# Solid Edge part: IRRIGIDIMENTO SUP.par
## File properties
Subject: IRRIGIDIMENTO SUP
Author: f_grande
Template: Normal.par
Last saved by: f_grande
Revision: 2
Application: Solid Edge
Material: MDF
Stile della faccia: Marroncino
Coef. of Thermal Exp: 0.0
Thermal Conductivity: 0.0
Specific Heat: 0.0
Modulus of Elasticity: 0.0
Poisson's Ratio: 0.0
Yield Stress: 0.0
Ultimate Stress: 0.0
Elongation: 0.0
Tipo di contenuto documento: 0
Densità: 750,000 kg/m^3
Precisione: 0,990
Document Number: KR0150
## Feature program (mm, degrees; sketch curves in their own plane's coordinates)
sketch for "unnamed Protrusion 1" plane through (0, 0, 0) normal (0, -1, 0) x-axis (1, 0, 0)
  line (-64.5, 20) -> (64.5, 20)
  line (64.5, 20) -> (64.5, -20)
  line (64.5, -20) -> (-64.5, -20)
  line (-64.5, -20) -> (-64.5, 20)
  dimension (linear) = 64.5
  dimension (linear) = 64.5
extrude "unnamed Protrusion 1" add finite 19 symmetric
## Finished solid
Body 1: solid body, 6 faces, 12 edges, 8 vertices.
  Faces by surface: plane 6
  Edges by curve: line 12
Bounding box of the edges (mm): 129.000 x 19.000 x 40.000, from (-64.5, -9.5, -20) to (64.5, 9.5, 20).
Planar faces by outward normal: +x 1, +y 1, +z 1, -x 1, -y 1, -z 1
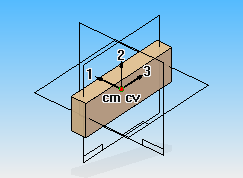
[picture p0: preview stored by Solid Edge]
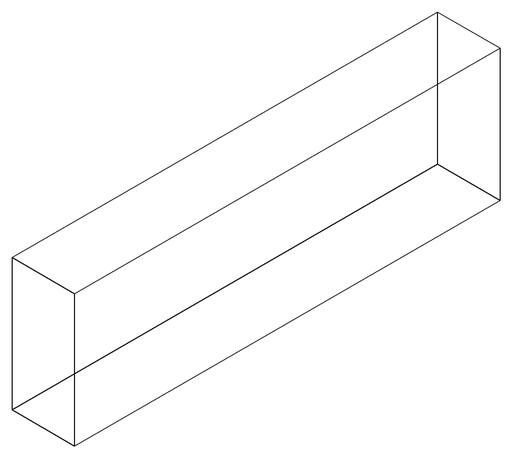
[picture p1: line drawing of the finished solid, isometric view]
